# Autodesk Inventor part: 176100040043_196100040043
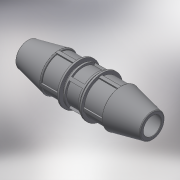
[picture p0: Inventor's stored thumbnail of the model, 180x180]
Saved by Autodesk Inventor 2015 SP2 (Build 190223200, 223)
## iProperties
Created: 2016-12
Part Number: 176100040043_196100040043
Material: Generic
Description: PLASSON UNIVERSAL SLIP REPAIR COUPLER 40-43 SERIES 17
Document SubType Name: Modeling
Designer: KIM
Mass: 305.707 g
Surface Area: 640.661 cm^2
Volume: 305.707 cm^3
Density: 1 g/cm^3
Appearance: Default
Author: KIM
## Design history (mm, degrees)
derived "17610.ipt"
feature "Solid1::17610.ipt"
tag "TaggingFeature1"
body "Solid1"
other parameters: "d5" = 151, "d11" = 37.75, "d12" = 3.02, "d13" = 60.2, "d14" = 62.5, "d15" = 43, "d16" = 42.14, "d17" = 71.2, "d20" = 75.65, "d21" = 80 deg, "d22" = 35.71429, "d23" = 0, "d25" = 360 deg, "d31" = 30.2, "d32" = 80.1, "d33" = 80 deg, "d34" = 40 deg, "d35" = 71.2, "d36" = 12.08, "d37" = 0, "d39" = 360 deg, "d41" = 2.5, "d43" = 360 deg, "d48" = 2.15, "d52" = 0.89, "d55" = 89, "d56" = 81.88, "d_" = 43, "E_" = 89, "l_" = 151
